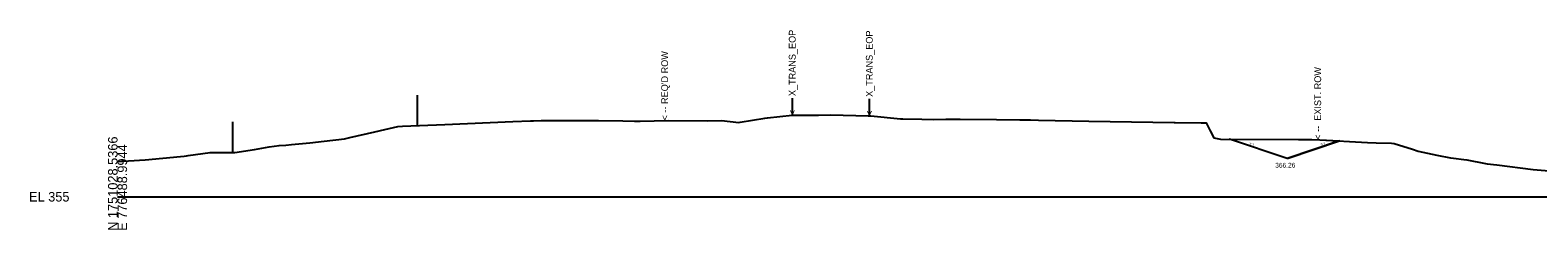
# Model space of a CAD drawing. Extents: x 776426 to 854588, y 1736205 to 1756790.
# Drawn here: x 804645.1 to 805088.3, y 1756705.1 to 1756763.6 of the extents above; entities that cross this region are included whole.
import ezdxf

# ---------------------------------------------------------------- set-up
doc = ezdxf.new("R2010")
doc.units = 0
for name, color, linetype in [('DTM CONTOURS_MAJOR_TX', 7, 'Continuous'), ('DTM_X_FLOW_ARROWS', 7, 'Continuous'), ('TRANS_UNPAVED_SHOULDERS', 7, 'Continuous'), ('X_TRANS_EOP', 7, 'Continuous'), ('XS_M_SHAPES_EARTHWORK', 7, 'Continuous'), ('XS_P_FINISHED_GRADE', 7, 'Continuous'), ('XS_P_ROW', 7, 'Continuous'), ('XS_P_TX_DCH', 7, 'Continuous'), ('XS_P_TX_FS_BS', 7, 'Continuous'), ('XS_X_PAVEMENT', 7, 'Continuous'), ('XS_X_ROW', 7, 'Continuous')]:
    doc.layers.add(name, color=color, linetype=linetype)

msp = doc.modelspace()

# ---------------------------------------------------------------- linework, layer by layer
at = {"layer": 'DTM CONTOURS_MAJOR_TX'}
msp.add_line((804670.79, 1756714.76), (805170.79, 1756714.76), dxfattribs=at)
at = {"layer": 'DTM_X_FLOW_ARROWS'}
msp.add_lwpolyline([(804670.79, 1756725.15), (804678.9, 1756725.62), (804689.3, 1756726.58), (804690.37, 1756726.66), (804691.01, 1756726.76), (804691.56, 1756726.85), (804695.9, 1756727.46), (804698, 1756727.77), (804699.86, 1756727.75), (804705.31, 1756727.8), (804711.04, 1756728.68), (804715.38, 1756729.44), (804718.32, 1756729.81), (804720.22, 1756729.93), (804721.94, 1756730.1), (804727.36, 1756730.57), (804731.51, 1756731.03), (804737.55, 1756731.74), (804739.07, 1756732.12), (804746.43, 1756733.8), (804749.38, 1756734.51), (804753.17, 1756735.43), (804754.59, 1756735.44), (804766.98, 1756735.96), (804787.03, 1756736.82), (804792.21, 1756737.05), (804793.02, 1756737.08), (804795.33, 1756737.14), (804807.12, 1756737.15), (804807.85, 1756737.12), (804812.17, 1756737.1), (804819.34, 1756737.03), (804822.72, 1756736.99), (804823.29, 1756736.99), (804824.46, 1756736.99), (804832.68, 1756737.19), (804844.35, 1756737.08), (804848.34, 1756737.11), (804853.47, 1756736.55), (804853.8, 1756736.61), (804861.07, 1756737.83), (804861.85, 1756737.94), (804869.12, 1756738.74), (804876.81, 1756738.71), (804880.51, 1756738.76), (804891.46, 1756738.52), (804891.77, 1756738.51), (804892.19, 1756738.47), (804900.97, 1756737.65), (804901.61, 1756737.62), (804907.23, 1756737.51), (804910.62, 1756737.47), (804914.29, 1756737.5), (804917.25, 1756737.49), (804918.46, 1756737.51), (804929.2, 1756737.4), (804936.01, 1756737.35), (804939.15, 1756737.31), (804941.53, 1756737.25), (804956.3, 1756736.96), (804981.35, 1756736.53), (804981.7, 1756736.55), (804989.37, 1756736.42), (804990.8, 1756736.47), (804992.01, 1756734.1), (804993.05, 1756732.09), (804995.03, 1756731.68), (805017.96, 1756731.55), (805021.89, 1756731.57), (805024.19, 1756731.47), (805038.18, 1756730.68), (805040.73, 1756730.59), (805045.32, 1756730.47), (805046.11, 1756730.41), (805051.44, 1756728.77), (805053.13, 1756728.18), (805058.65, 1756726.95), (805062.6, 1756726.2), (805063.52, 1756726.08), (805066.57, 1756725.71), (805067.46, 1756725.6), (805072.89, 1756724.55), (805073.41, 1756724.47), (805076.26, 1756724.17), (805086.95, 1756722.76), (805095.07, 1756722.05)], dxfattribs=at)
at = {"layer": 'TRANS_UNPAVED_SHOULDERS'}
for p, q in [((804758.87, 1756744.62), (804758.87, 1756735.62)), ((804758.87, 1756744.62), (804758.87, 1756735.62)), ((804704.6, 1756736.8), (804704.6, 1756727.8)), ((804704.6, 1756736.8), (804704.6, 1756727.8))]:
    msp.add_line(p, q, dxfattribs=at)
at = {"layer": 'X_TRANS_EOP'}
for p, q in [((804869.12, 1756743.74), (804869.12, 1756738.74)), ((804869.12, 1756743.74), (804869.12, 1756738.74)), ((804891.77, 1756743.51), (804891.77, 1756738.51)), ((804891.77, 1756743.51), (804891.77, 1756738.51))]:
    msp.add_line(p, q, dxfattribs=at)
at = {"layer": 'XS_M_SHAPES_EARTHWORK'}
msp.add_lwpolyline([(805014.59, 1756726.02), (804997.65, 1756731.67), (805017.96, 1756731.55), (805021.89, 1756731.57), (805024.19, 1756731.47), (805029.96, 1756731.15)], close=True, dxfattribs=at)
at = {"layer": 'XS_P_FINISHED_GRADE'}
for q in [(804997.65, 1756731.67), (805029.96, 1756731.15)]:
    msp.add_line((805014.59, 1756726.02), q, dxfattribs=at)

# ---------------------------------------------------------------- texts
at = {"layer": 'DTM CONTOURS_MAJOR_TX'}
for s, p in [('N 1751028.5366', (804670.79, 1756704.76)), ('E 776488.9944', (804673.59, 1756704.76))]:
    msp.add_text(s, height=2.8, rotation=90, dxfattribs=at).set_placement(p)
msp.add_text('EL 355', height=2.8, dxfattribs=at).set_placement((804644.79, 1756713.36))
at = {"layer": 'XS_P_ROW'}
msp.add_text("< -- REQ'D ROW", height=2, rotation=90, dxfattribs=at).set_placement((804832.62, 1756737.16))
at = {"layer": 'XS_P_TX_DCH'}
msp.add_text('366.26', height=1.4, dxfattribs=at).set_placement((805011.1, 1756723.32))
at = {"layer": 'XS_P_TX_FS_BS'}
for rotation, p in [(341.5651, (805003.32, 1756730)), (18.4349, (805024.57, 1756729.57))]:
    msp.add_text('3:1', height=0.8, rotation=rotation, dxfattribs=at).set_placement(p)
at = {"layer": 'XS_X_PAVEMENT'}
for p in [(804870.12, 1756738.74), (804892.77, 1756738.51)]:
    msp.add_text('< --  X_TRANS_EOP', height=2, rotation=90, dxfattribs=at).set_placement(p)
at = {"layer": 'XS_X_ROW'}
msp.add_text('< --  EXIST. ROW', height=2, rotation=90, dxfattribs=at).set_placement((805024.6, 1756731.5))

doc.saveas('drawing.dxf')
